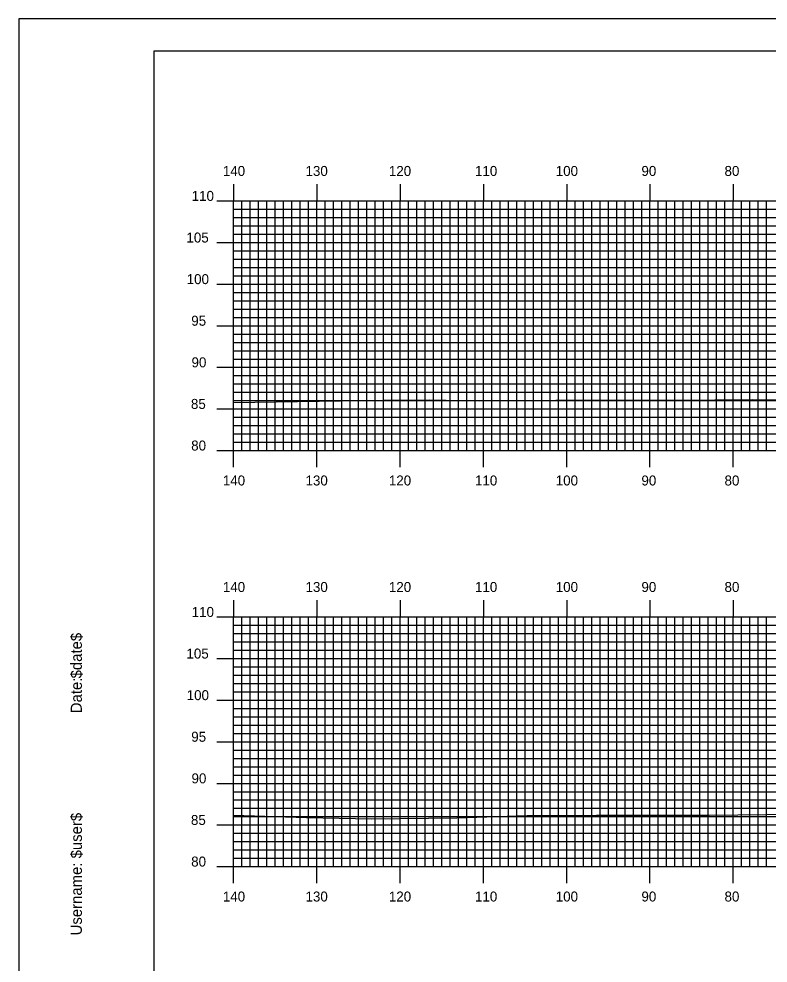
# Model space of a CAD drawing. Extents: x 1762184 to 1762528, y 442591 to 442811.
# Drawn here: x 1762184.5 to 1762274.5, y 442697.1 to 442810.5 of the extents above; entities that cross this region are included whole.
import ezdxf

# ---------------------------------------------------------------- set-up
doc = ezdxf.new("R2010")
doc.units = 0
for name, color, linetype in [('BORDER', 7, 'Continuous'), ('H_V ANNOTATION', 7, 'Continuous'), ('MAJOR', 7, 'Continuous'), ('MINOR', 7, 'Continuous'), ('PLOT BOUNDARY', 7, 'Continuous'), ('S_Roadway_Centerline', 7, 'Continuous')]:
    doc.layers.add(name, color=color, linetype=linetype)

msp = doc.modelspace()

# ---------------------------------------------------------------- linework, layer by layer
at = {"layer": 'BORDER'}
msp.add_lwpolyline([(1762200.67, 442596.67), (1762520.67, 442596.67), (1762520.67, 442806.67), (1762200.67, 442806.67)], close=True, dxfattribs=at)
at = {"layer": 'MAJOR'}
for p, q in [((1762210.27, 442790.67), (1762210.27, 442788.67)), ((1762220.27, 442790.67), (1762220.27, 442788.67)), ((1762230.27, 442790.67), (1762230.27, 442788.67)), ((1762240.27, 442790.67), (1762240.27, 442788.67)), ((1762250.27, 442790.67), (1762250.27, 442788.67)), ((1762260.27, 442790.67), (1762260.27, 442788.67)), ((1762270.27, 442790.67), (1762270.27, 442788.67)), ((1762208.26, 442788.67), (1762210.27, 442788.67)), ((1762210.27, 442788.67), (1762490.27, 442788.67)), ((1762210.27, 442758.67), (1762210.27, 442788.67)), ((1762210.27, 442758.67), (1762210.27, 442788.67)), ((1762210.27, 442788.67), (1762490.27, 442788.67)), ((1762220.27, 442758.67), (1762220.27, 442788.67)), ((1762230.27, 442758.67), (1762230.27, 442788.67)), ((1762240.27, 442758.67), (1762240.27, 442788.67)), ((1762250.27, 442758.67), (1762250.27, 442788.67)), ((1762260.27, 442758.67), (1762260.27, 442788.67)), ((1762270.27, 442758.67), (1762270.27, 442788.67)), ((1762208.26, 442783.67), (1762210.27, 442783.67)), ((1762210.27, 442783.67), (1762490.27, 442783.67)), ((1762208.26, 442778.67), (1762210.27, 442778.67)), ((1762210.27, 442778.67), (1762490.27, 442778.67)), ((1762208.26, 442773.67), (1762210.27, 442773.67)), ((1762210.27, 442773.67), (1762490.27, 442773.67)), ((1762208.26, 442768.67), (1762210.27, 442768.67)), ((1762210.27, 442768.67), (1762490.27, 442768.67)), ((1762208.26, 442763.67), (1762210.27, 442763.67)), ((1762210.27, 442763.67), (1762490.27, 442763.67)), ((1762208.26, 442758.67), (1762210.27, 442758.67)), ((1762210.27, 442758.67), (1762490.27, 442758.67)), ((1762210.27, 442758.67), (1762490.27, 442758.67)), ((1762210.27, 442756.66), (1762210.27, 442758.67)), ((1762220.27, 442756.66), (1762220.27, 442758.67)), ((1762230.27, 442756.66), (1762230.27, 442758.67)), ((1762240.27, 442756.66), (1762240.27, 442758.67)), ((1762250.27, 442756.66), (1762250.27, 442758.67)), ((1762260.27, 442756.66), (1762260.27, 442758.67)), ((1762270.27, 442756.66), (1762270.27, 442758.67)), ((1762210.27, 442740.67), (1762210.27, 442738.67)), ((1762220.27, 442740.67), (1762220.27, 442738.67)), ((1762230.27, 442740.67), (1762230.27, 442738.67)), ((1762240.27, 442740.67), (1762240.27, 442738.67)), ((1762250.27, 442740.67), (1762250.27, 442738.67)), ((1762260.27, 442740.67), (1762260.27, 442738.67)), ((1762270.27, 442740.67), (1762270.27, 442738.67)), ((1762208.26, 442738.67), (1762210.27, 442738.67)), ((1762210.27, 442738.67), (1762490.27, 442738.67)), ((1762210.27, 442708.67), (1762210.27, 442738.67)), ((1762210.27, 442708.67), (1762210.27, 442738.67)), ((1762210.27, 442738.67), (1762490.27, 442738.67)), ((1762220.27, 442708.67), (1762220.27, 442738.67)), ((1762230.27, 442708.67), (1762230.27, 442738.67)), ((1762240.27, 442708.67), (1762240.27, 442738.67)), ((1762250.27, 442708.67), (1762250.27, 442738.67)), ((1762260.27, 442708.67), (1762260.27, 442738.67)), ((1762270.27, 442708.67), (1762270.27, 442738.67)), ((1762208.26, 442733.67), (1762210.27, 442733.67)), ((1762210.27, 442733.67), (1762490.27, 442733.67)), ((1762208.26, 442728.67), (1762210.27, 442728.67)), ((1762210.27, 442728.67), (1762490.27, 442728.67)), ((1762208.26, 442723.67), (1762210.27, 442723.67)), ((1762210.27, 442723.67), (1762490.27, 442723.67)), ((1762208.26, 442718.67), (1762210.27, 442718.67)), ((1762210.27, 442718.67), (1762490.27, 442718.67)), ((1762208.26, 442713.67), (1762210.27, 442713.67)), ((1762210.27, 442713.67), (1762490.27, 442713.67)), ((1762208.26, 442708.67), (1762210.27, 442708.67)), ((1762210.27, 442708.67), (1762490.27, 442708.67)), ((1762210.27, 442708.67), (1762490.27, 442708.67)), ((1762210.27, 442706.66), (1762210.27, 442708.67)), ((1762220.27, 442706.66), (1762220.27, 442708.67)), ((1762230.27, 442706.66), (1762230.27, 442708.67)), ((1762240.27, 442706.66), (1762240.27, 442708.67)), ((1762250.27, 442706.66), (1762250.27, 442708.67)), ((1762260.27, 442706.66), (1762260.27, 442708.67)), ((1762270.27, 442706.66), (1762270.27, 442708.67))]:
    msp.add_line(p, q, dxfattribs=at)
at = {"layer": 'MINOR'}
for p, q in [((1762211.27, 442758.67), (1762211.27, 442788.67)), ((1762212.27, 442758.67), (1762212.27, 442788.67)), ((1762213.27, 442758.67), (1762213.27, 442788.67)), ((1762214.27, 442758.67), (1762214.27, 442788.67)), ((1762215.27, 442758.67), (1762215.27, 442788.67)), ((1762216.27, 442758.67), (1762216.27, 442788.67)), ((1762217.27, 442758.67), (1762217.27, 442788.67)), ((1762218.27, 442758.67), (1762218.27, 442788.67)), ((1762219.27, 442758.67), (1762219.27, 442788.67)), ((1762221.27, 442758.67), (1762221.27, 442788.67)), ((1762222.27, 442758.67), (1762222.27, 442788.67)), ((1762223.27, 442758.67), (1762223.27, 442788.67)), ((1762224.27, 442758.67), (1762224.27, 442788.67)), ((1762225.27, 442758.67), (1762225.27, 442788.67)), ((1762226.27, 442758.67), (1762226.27, 442788.67)), ((1762227.27, 442758.67), (1762227.27, 442788.67)), ((1762228.27, 442758.67), (1762228.27, 442788.67)), ((1762229.27, 442758.67), (1762229.27, 442788.67)), ((1762231.27, 442758.67), (1762231.27, 442788.67)), ((1762232.27, 442758.67), (1762232.27, 442788.67)), ((1762233.27, 442758.67), (1762233.27, 442788.67)), ((1762234.27, 442758.67), (1762234.27, 442788.67)), ((1762235.27, 442758.67), (1762235.27, 442788.67)), ((1762236.27, 442758.67), (1762236.27, 442788.67)), ((1762237.27, 442758.67), (1762237.27, 442788.67)), ((1762238.27, 442758.67), (1762238.27, 442788.67)), ((1762239.27, 442758.67), (1762239.27, 442788.67)), ((1762241.27, 442758.67), (1762241.27, 442788.67)), ((1762242.27, 442758.67), (1762242.27, 442788.67)), ((1762243.27, 442758.67), (1762243.27, 442788.67)), ((1762244.27, 442758.67), (1762244.27, 442788.67)), ((1762245.27, 442758.67), (1762245.27, 442788.67)), ((1762246.27, 442758.67), (1762246.27, 442788.67)), ((1762247.27, 442758.67), (1762247.27, 442788.67)), ((1762248.27, 442758.67), (1762248.27, 442788.67)), ((1762249.27, 442758.67), (1762249.27, 442788.67)), ((1762251.27, 442758.67), (1762251.27, 442788.67)), ((1762252.27, 442758.67), (1762252.27, 442788.67)), ((1762253.27, 442758.67), (1762253.27, 442788.67)), ((1762254.27, 442758.67), (1762254.27, 442788.67)), ((1762255.27, 442758.67), (1762255.27, 442788.67)), ((1762256.27, 442758.67), (1762256.27, 442788.67)), ((1762257.27, 442758.67), (1762257.27, 442788.67)), ((1762258.27, 442758.67), (1762258.27, 442788.67)), ((1762259.27, 442758.67), (1762259.27, 442788.67)), ((1762261.27, 442758.67), (1762261.27, 442788.67)), ((1762262.27, 442758.67), (1762262.27, 442788.67)), ((1762263.27, 442758.67), (1762263.27, 442788.67)), ((1762264.27, 442758.67), (1762264.27, 442788.67)), ((1762265.27, 442758.67), (1762265.27, 442788.67)), ((1762266.27, 442758.67), (1762266.27, 442788.67)), ((1762267.27, 442758.67), (1762267.27, 442788.67)), ((1762268.27, 442758.67), (1762268.27, 442788.67)), ((1762269.27, 442758.67), (1762269.27, 442788.67)), ((1762271.27, 442758.67), (1762271.27, 442788.67)), ((1762272.27, 442758.67), (1762272.27, 442788.67)), ((1762273.27, 442758.67), (1762273.27, 442788.67)), ((1762274.27, 442758.67), (1762274.27, 442788.67)), ((1762210.27, 442787.67), (1762490.27, 442787.67)), ((1762210.27, 442787.67), (1762212.27, 442787.67)), ((1762210.27, 442786.67), (1762490.27, 442786.67)), ((1762210.27, 442786.67), (1762212.27, 442786.67)), ((1762210.27, 442785.67), (1762490.27, 442785.67)), ((1762210.27, 442785.67), (1762212.27, 442785.67)), ((1762210.27, 442784.67), (1762490.27, 442784.67)), ((1762210.27, 442784.67), (1762212.27, 442784.67)), ((1762210.27, 442782.67), (1762490.27, 442782.67)), ((1762210.27, 442782.67), (1762212.27, 442782.67)), ((1762210.27, 442781.67), (1762490.27, 442781.67)), ((1762210.27, 442781.67), (1762212.27, 442781.67)), ((1762210.27, 442780.67), (1762490.27, 442780.67)), ((1762210.27, 442780.67), (1762212.27, 442780.67)), ((1762210.27, 442779.67), (1762490.27, 442779.67)), ((1762210.27, 442779.67), (1762212.27, 442779.67)), ((1762210.27, 442777.67), (1762490.27, 442777.67)), ((1762210.27, 442777.67), (1762212.27, 442777.67)), ((1762210.27, 442776.67), (1762490.27, 442776.67)), ((1762210.27, 442776.67), (1762212.27, 442776.67)), ((1762210.27, 442775.67), (1762490.27, 442775.67)), ((1762210.27, 442775.67), (1762212.27, 442775.67)), ((1762210.27, 442774.67), (1762490.27, 442774.67)), ((1762210.27, 442774.67), (1762212.27, 442774.67)), ((1762210.27, 442772.67), (1762490.27, 442772.67)), ((1762210.27, 442772.67), (1762212.27, 442772.67)), ((1762210.27, 442771.67), (1762490.27, 442771.67)), ((1762210.27, 442771.67), (1762212.27, 442771.67)), ((1762210.27, 442770.67), (1762490.27, 442770.67)), ((1762210.27, 442770.67), (1762212.27, 442770.67)), ((1762210.27, 442769.67), (1762490.27, 442769.67)), ((1762210.27, 442769.67), (1762212.27, 442769.67)), ((1762210.27, 442767.67), (1762490.27, 442767.67)), ((1762210.27, 442767.67), (1762212.27, 442767.67)), ((1762210.27, 442766.67), (1762490.27, 442766.67)), ((1762210.27, 442766.67), (1762212.27, 442766.67)), ((1762210.27, 442765.67), (1762490.27, 442765.67)), ((1762210.27, 442765.67), (1762212.27, 442765.67)), ((1762210.27, 442764.67), (1762490.27, 442764.67)), ((1762210.27, 442764.67), (1762212.27, 442764.67)), ((1762210.27, 442762.67), (1762490.27, 442762.67)), ((1762210.27, 442762.67), (1762212.27, 442762.67)), ((1762210.27, 442761.67), (1762490.27, 442761.67)), ((1762210.27, 442761.67), (1762212.27, 442761.67)), ((1762210.27, 442760.67), (1762490.27, 442760.67)), ((1762210.27, 442760.67), (1762212.27, 442760.67)), ((1762210.27, 442759.67), (1762490.27, 442759.67)), ((1762210.27, 442759.67), (1762212.27, 442759.67)), ((1762211.27, 442708.67), (1762211.27, 442738.67)), ((1762212.27, 442708.67), (1762212.27, 442738.67)), ((1762213.27, 442708.67), (1762213.27, 442738.67)), ((1762214.27, 442708.67), (1762214.27, 442738.67)), ((1762215.27, 442708.67), (1762215.27, 442738.67)), ((1762216.27, 442708.67), (1762216.27, 442738.67)), ((1762217.27, 442708.67), (1762217.27, 442738.67)), ((1762218.27, 442708.67), (1762218.27, 442738.67)), ((1762219.27, 442708.67), (1762219.27, 442738.67)), ((1762221.27, 442708.67), (1762221.27, 442738.67)), ((1762222.27, 442708.67), (1762222.27, 442738.67)), ((1762223.27, 442708.67), (1762223.27, 442738.67)), ((1762224.27, 442708.67), (1762224.27, 442738.67)), ((1762225.27, 442708.67), (1762225.27, 442738.67)), ((1762226.27, 442708.67), (1762226.27, 442738.67)), ((1762227.27, 442708.67), (1762227.27, 442738.67)), ((1762228.27, 442708.67), (1762228.27, 442738.67)), ((1762229.27, 442708.67), (1762229.27, 442738.67)), ((1762231.27, 442708.67), (1762231.27, 442738.67)), ((1762232.27, 442708.67), (1762232.27, 442738.67)), ((1762233.27, 442708.67), (1762233.27, 442738.67)), ((1762234.27, 442708.67), (1762234.27, 442738.67)), ((1762235.27, 442708.67), (1762235.27, 442738.67)), ((1762236.27, 442708.67), (1762236.27, 442738.67)), ((1762237.27, 442708.67), (1762237.27, 442738.67)), ((1762238.27, 442708.67), (1762238.27, 442738.67)), ((1762239.27, 442708.67), (1762239.27, 442738.67)), ((1762241.27, 442708.67), (1762241.27, 442738.67)), ((1762242.27, 442708.67), (1762242.27, 442738.67)), ((1762243.27, 442708.67), (1762243.27, 442738.67)), ((1762244.27, 442708.67), (1762244.27, 442738.67)), ((1762245.27, 442708.67), (1762245.27, 442738.67)), ((1762246.27, 442708.67), (1762246.27, 442738.67)), ((1762247.27, 442708.67), (1762247.27, 442738.67)), ((1762248.27, 442708.67), (1762248.27, 442738.67)), ((1762249.27, 442708.67), (1762249.27, 442738.67)), ((1762251.27, 442708.67), (1762251.27, 442738.67)), ((1762252.27, 442708.67), (1762252.27, 442738.67)), ((1762253.27, 442708.67), (1762253.27, 442738.67)), ((1762254.27, 442708.67), (1762254.27, 442738.67)), ((1762255.27, 442708.67), (1762255.27, 442738.67)), ((1762256.27, 442708.67), (1762256.27, 442738.67)), ((1762257.27, 442708.67), (1762257.27, 442738.67)), ((1762258.27, 442708.67), (1762258.27, 442738.67)), ((1762259.27, 442708.67), (1762259.27, 442738.67)), ((1762261.27, 442708.67), (1762261.27, 442738.67)), ((1762262.27, 442708.67), (1762262.27, 442738.67)), ((1762263.27, 442708.67), (1762263.27, 442738.67)), ((1762264.27, 442708.67), (1762264.27, 442738.67)), ((1762265.27, 442708.67), (1762265.27, 442738.67)), ((1762266.27, 442708.67), (1762266.27, 442738.67)), ((1762267.27, 442708.67), (1762267.27, 442738.67)), ((1762268.27, 442708.67), (1762268.27, 442738.67)), ((1762269.27, 442708.67), (1762269.27, 442738.67)), ((1762271.27, 442708.67), (1762271.27, 442738.67)), ((1762272.27, 442708.67), (1762272.27, 442738.67)), ((1762273.27, 442708.67), (1762273.27, 442738.67)), ((1762274.27, 442708.67), (1762274.27, 442738.67)), ((1762210.27, 442737.67), (1762490.27, 442737.67)), ((1762210.27, 442737.67), (1762212.27, 442737.67)), ((1762210.27, 442736.67), (1762490.27, 442736.67)), ((1762210.27, 442736.67), (1762212.27, 442736.67)), ((1762210.27, 442735.67), (1762490.27, 442735.67)), ((1762210.27, 442735.67), (1762212.27, 442735.67)), ((1762210.27, 442734.67), (1762490.27, 442734.67)), ((1762210.27, 442734.67), (1762212.27, 442734.67)), ((1762210.27, 442732.67), (1762490.27, 442732.67)), ((1762210.27, 442732.67), (1762212.27, 442732.67)), ((1762210.27, 442731.67), (1762490.27, 442731.67)), ((1762210.27, 442731.67), (1762212.27, 442731.67)), ((1762210.27, 442730.67), (1762490.27, 442730.67)), ((1762210.27, 442730.67), (1762212.27, 442730.67)), ((1762210.27, 442729.67), (1762490.27, 442729.67)), ((1762210.27, 442729.67), (1762212.27, 442729.67)), ((1762210.27, 442727.67), (1762490.27, 442727.67)), ((1762210.27, 442727.67), (1762212.27, 442727.67)), ((1762210.27, 442726.67), (1762490.27, 442726.67)), ((1762210.27, 442726.67), (1762212.27, 442726.67)), ((1762210.27, 442725.67), (1762490.27, 442725.67)), ((1762210.27, 442725.67), (1762212.27, 442725.67)), ((1762210.27, 442724.67), (1762490.27, 442724.67)), ((1762210.27, 442724.67), (1762212.27, 442724.67)), ((1762210.27, 442722.67), (1762490.27, 442722.67)), ((1762210.27, 442722.67), (1762212.27, 442722.67)), ((1762210.27, 442721.67), (1762490.27, 442721.67)), ((1762210.27, 442721.67), (1762212.27, 442721.67)), ((1762210.27, 442720.67), (1762490.27, 442720.67)), ((1762210.27, 442720.67), (1762212.27, 442720.67)), ((1762210.27, 442719.67), (1762490.27, 442719.67)), ((1762210.27, 442719.67), (1762212.27, 442719.67)), ((1762210.27, 442717.67), (1762490.27, 442717.67)), ((1762210.27, 442717.67), (1762212.27, 442717.67)), ((1762210.27, 442716.67), (1762490.27, 442716.67)), ((1762210.27, 442716.67), (1762212.27, 442716.67)), ((1762210.27, 442715.67), (1762490.27, 442715.67)), ((1762210.27, 442715.67), (1762212.27, 442715.67)), ((1762210.27, 442714.67), (1762490.27, 442714.67)), ((1762210.27, 442714.67), (1762212.27, 442714.67)), ((1762210.27, 442712.67), (1762490.27, 442712.67)), ((1762210.27, 442712.67), (1762212.27, 442712.67)), ((1762210.27, 442711.67), (1762490.27, 442711.67)), ((1762210.27, 442711.67), (1762212.27, 442711.67)), ((1762210.27, 442710.67), (1762490.27, 442710.67)), ((1762210.27, 442710.67), (1762212.27, 442710.67)), ((1762210.27, 442709.67), (1762490.27, 442709.67)), ((1762210.27, 442709.67), (1762212.27, 442709.67))]:
    msp.add_line(p, q, dxfattribs=at)
at = {"layer": 'PLOT BOUNDARY'}
msp.add_lwpolyline([(1762184.48, 442590.55), (1762524.48, 442590.55), (1762524.48, 442810.55), (1762184.48, 442810.55)], close=True, dxfattribs=at)
at = {"layer": 'S_Roadway_Centerline'}
for points in [[(1762210.27, 442764.43), (1762228.23, 442764.73), (1762233.82, 442764.78), (1762239.74, 442764.65), (1762248.97, 442764.72), (1762253.17, 442764.72), (1762263.54, 442764.73), (1762272.55, 442764.79), (1762280.38, 442764.77), (1762287.62, 442764.62), (1762292.89, 442764.49), (1762309.79, 442764.84), (1762312.42, 442764.95), (1762318.72, 442764.73), (1762332.24, 442764.31), (1762334.82, 442764.33), (1762352.11, 442764.85), (1762359.24, 442764.67), (1762369.65, 442764.78), (1762371.28, 442764.74), (1762373.9, 442764.79), (1762389.4, 442764.82), (1762398, 442764.77), (1762405.61, 442764.58)], [(1762210.27, 442714.83), (1762219.02, 442714.55), (1762226.86, 442714.42), (1762237.06, 442714.53), (1762245.51, 442714.79), (1762253.86, 442714.83), (1762265.5, 442714.85), (1762267.38, 442714.83), (1762277.69, 442714.96)]]:
    msp.add_lwpolyline(points, dxfattribs=at)

# ---------------------------------------------------------------- texts
at = {"layer": 'BORDER'}
for s, p in [('$date$', (1762192.04, 442731.28)), ('Date:', (1762192.04, 442727.1)), ('$user$', (1762192.04, 442709.65)), ('Username:', (1762192.04, 442700.4))]:
    msp.add_text(s, height=1.339, rotation=90, dxfattribs=at).set_placement(p)
at = {"layer": 'H_V ANNOTATION'}
for s, p in [('140', (1762208.97, 442791.67)), ('130', (1762218.9, 442791.67)), ('120', (1762228.91, 442791.67)), ('110', (1762239.25, 442791.67)), ('100', (1762248.95, 442791.67)), ('90', (1762259.24, 442791.67)), ('80', (1762269.22, 442791.67)), ('110', (1762205.23, 442788.67)), ('105', (1762204.6, 442783.67)), ('100', (1762204.63, 442778.67)), ('95', (1762205.18, 442773.67)), ('90', (1762205.21, 442768.67)), ('85', (1762205.14, 442763.67)), ('80', (1762205.17, 442758.67)), ('140', (1762208.97, 442754.47)), ('130', (1762218.9, 442754.47)), ('120', (1762228.91, 442754.47)), ('110', (1762239.25, 442754.47)), ('100', (1762248.95, 442754.47)), ('90', (1762259.24, 442754.47)), ('80', (1762269.22, 442754.47)), ('140', (1762208.97, 442741.67)), ('130', (1762218.9, 442741.67)), ('120', (1762228.91, 442741.67)), ('110', (1762239.25, 442741.67)), ('100', (1762248.95, 442741.67)), ('90', (1762259.24, 442741.67)), ('80', (1762269.22, 442741.67)), ('110', (1762205.23, 442738.67)), ('105', (1762204.6, 442733.67)), ('100', (1762204.63, 442728.67)), ('95', (1762205.18, 442723.67)), ('90', (1762205.21, 442718.67)), ('85', (1762205.14, 442713.67)), ('80', (1762205.17, 442708.67)), ('140', (1762208.97, 442704.47)), ('130', (1762218.9, 442704.47)), ('120', (1762228.91, 442704.47)), ('110', (1762239.25, 442704.47)), ('100', (1762248.95, 442704.47)), ('90', (1762259.24, 442704.47)), ('80', (1762269.22, 442704.47))]:
    msp.add_text(s, height=1.2, dxfattribs=at).set_placement(p)
at = {"layer": 'MAJOR'}
for p in [(1762210.26, 442758.67), (1762210.26, 442708.67)]:
    msp.add_text('-', height=0.012, dxfattribs=at).set_placement(p)

doc.saveas('drawing.dxf')
